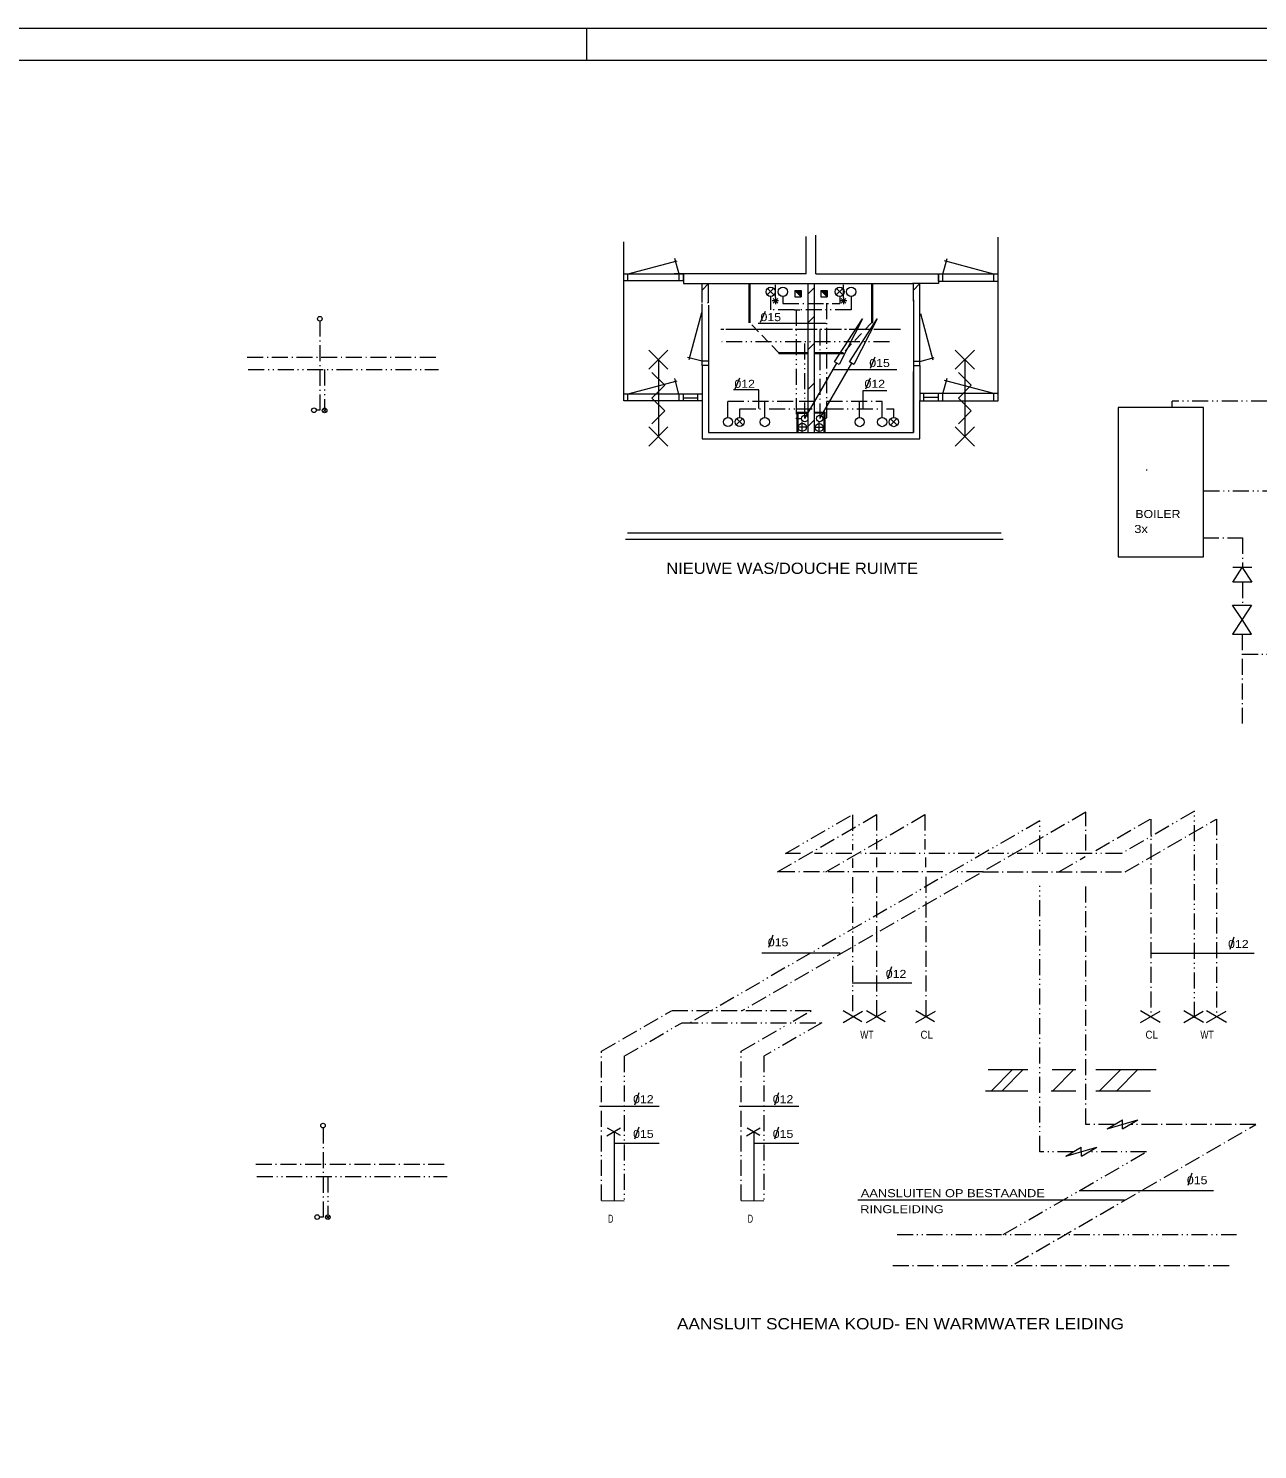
# Model space of a CAD drawing. Extents: x 295824 to 414724, y 24924 to 109024.
# Drawn here: x 355274 to 393674, y 64629 to 109024 of the extents above; entities that cross this region are included whole.
import ezdxf

# ---------------------------------------------------------------- set-up
doc = ezdxf.new("R2010")
doc.units = 0
doc.header["$LTSCALE"] = 100
for name, pattern in [('DASH_DOUBLE_DOT', [9.2, 5, -1.2, 0.3, -1.2, 0.3, -1.2]), ('DOT_DASHED', [7.7, 5, -1.2, 0.3, -1.2]), ('MEDIUM_DASHED', [4.5, 3, -1.5])]:
    doc.linetypes.add(name, pattern=pattern)
for name, color, linetype, lineweight in [('1', 7, 'Continuous', 13), ('16', 7, 'Continuous', 13), ('30', 7, 'Continuous', 13), ('61', 7, 'Continuous', 13)]:
    doc.layers.add(name, color=color, linetype=linetype, lineweight=lineweight)

msp = doc.modelspace()

# ---------------------------------------------------------------- hatches: boundary and pattern name
at = {"layer": '1'}
for points in [[(379418.1, 100633.9), (379218.1, 100833.9), (379418.1, 100833.9)], [(380224.2, 100633.9), (380024.2, 100833.9), (380224.2, 100833.9)]]:
    msp.add_hatch(color=256, dxfattribs=at).paths.add_polyline_path(points)

# ---------------------------------------------------------------- linework, layer by layer
for p, q in [((372723.6, 108023.8), (372723.6, 109023.8)), ((379870, 101352.7), (379870, 102562.3)), ((373870.5, 97608.1), (373873.8, 102362.2)), ((379570, 101352.7), (379570, 102529)), ((385568.8, 97615.9), (385568.8, 102497.8)), ((374009.9, 101355.3), (375544.5, 101766.5)), ((375599.1, 101351), (375469, 101836.4)), ((383842.7, 101347), (383972.8, 101832.4)), ((385431.8, 101351.3), (383897.2, 101762.5)), ((374004.8, 101134.9), (374004.8, 101354.9)), ((379570, 101352.7), (375450, 101352.7)), ((375604.8, 101134.9), (375604.8, 101354.9)), ((375738.8, 101134.9), (375738.8, 101355)), ((379870, 101352.7), (385568.7, 101352.7)), ((379870, 101352.7), (383754.9, 101352.7)), ((383703, 101131), (383703, 101351)), ((383837, 101131), (383837, 101351)), ((385437, 101131), (385437, 101351)), ((385568.8, 101131.7), (385568.8, 101352.4)), ((375734.5, 101135.7), (373873, 101135.7)), ((375740.5, 101052.7), (382920.9, 101052.7)), ((376320.1, 100458.9), (376320.1, 101052.7)), ((376320.2, 100851.2), (376521, 101052)), ((376517.6, 100464.5), (376517.6, 101052.7)), ((377785.5, 99826), (377785.5, 101042.9)), ((377821.5, 99826), (377821.5, 101042.9)), ((378611.3, 100615.1), (378611.3, 101015.1)), ((379620, 101052.7), (379620, 99815.2)), ((379620.9, 100722.9), (379817.9, 100919.8)), ((379820, 101052.7), (379820, 100575.7)), ((380740.2, 100615.1), (380740.2, 101015.1)), ((381621.1, 99838.3), (381621.1, 101047.9)), ((381657.1, 99838.3), (381657.1, 101047.9)), ((382920.9, 100504.8), (382920.9, 101053.4)), ((382921.2, 100851.2), (383122, 101052)), ((383120.4, 100521.4), (383120.4, 101052.7)), ((383707.2, 101131.7), (385568.8, 101131.7)), ((376319.7, 98492.6), (376319.7, 100418)), ((376489, 100447.3), (376518.2, 100476.6)), ((376519.7, 100374.5), (376519.7, 98492.6)), ((378711.3, 100515.1), (378511.3, 100515.1)), ((378682, 100585.9), (378540.5, 100444.4)), ((378682, 100444.4), (378540.5, 100585.9)), ((378611.3, 100615.1), (378611.3, 100415.1)), ((379820, 100629.6), (379820, 96402.7)), ((380840.2, 100515.1), (380640.2, 100515.1)), ((380810.9, 100585.9), (380669.5, 100444.4)), ((380810.9, 100444.4), (380669.5, 100585.9)), ((380740.2, 100615.1), (380740.2, 100415.1)), ((382920, 100548.5), (382920, 98491.9)), ((383120.2, 99693.6), (383120.2, 100570.2)), ((376300, 100144.2), (375906.4, 98675)), ((379620, 99979.6), (379620, 96402.7)), ((379620.9, 99827.7), (379817.9, 100024.7)), ((383147.1, 100115.4), (383533.2, 98674.3)), ((381621.1, 99838.3), (381657.1, 99838.3)), ((383120, 98490.3), (383120, 99786.1)), ((379620.9, 98982.6), (379817.9, 99179.6)), ((374653.8, 98376.3), (375253.8, 98976.3)), ((375253.8, 98376.3), (374653.8, 98976.3)), ((374953.8, 98676.3), (374953.8, 96276.3)), ((376320.2, 98624.6), (375865.6, 98746.4)), ((376519.5, 98626.6), (376320.8, 98626.6)), ((379619.3, 98854.3), (378718.6, 98854.3)), ((380722, 98890.3), (379821.9, 98890.3)), ((380722, 98854.3), (379821.9, 98854.3)), ((380722, 98890.3), (380722, 98854.3)), ((382920.2, 98625.9), (383118.9, 98625.9)), ((383119.4, 98623.9), (383574.1, 98745.7)), ((384229.2, 98376.3), (384829.2, 98976.3)), ((384829.2, 98376.3), (384229.2, 98976.3)), ((384529.2, 98676.3), (384529.2, 96276.3)), ((376519.7, 98492.6), (376319.7, 98492.6)), ((376320, 98487.5), (376320, 96913.2)), ((382920, 98491.9), (383120, 98491.9)), ((383120, 98491.9), (383120, 97602.7)), ((374007.5, 97607), (375542.1, 98018.2)), ((375596.6, 97602.7), (375466.5, 98088.1)), ((379620.9, 97742.7), (379817.9, 97939.7)), ((383842.7, 97610.4), (383972.8, 98095.9)), ((385431.8, 97614.8), (383897.2, 98025.9)), ((374002.3, 97386.7), (374002.3, 97606.7)), ((375602.3, 97386.7), (375602.3, 97606.7)), ((375736.3, 97386.7), (375736.3, 97606.7)), ((375737.9, 97488.2), (376187.3, 97488.2)), ((376187.3, 97386.7), (376187.3, 97606.7)), ((376320, 97402.7), (376320, 96202.7)), ((383120, 96202.7), (383120, 97402.7)), ((383252, 97394.4), (383252, 97614.4)), ((383701.4, 97495.9), (383252, 97495.9)), ((383703, 97394.4), (383703, 97614.4)), ((383837, 97394.4), (383837, 97614.4)), ((385437, 97394.4), (385437, 97614.4)), ((379283.4, 97034.7), (379619, 97034.7)), ((379283.4, 97034.7), (379283.4, 96407.2)), ((379313.4, 97004.7), (379621.3, 97004.7)), ((379313.4, 97004.7), (379313.4, 96406.6)), ((379623.7, 96586.7), (379818.3, 96781.2)), ((379821.3, 97037.4), (380159.6, 97037.4)), ((380129.8, 97007.1), (379823.1, 97007.1)), ((380129.8, 96403.9), (380129.8, 97007.1)), ((380159.6, 96402.7), (380159.6, 97037.4)), ((374653.8, 95976.3), (375253.8, 96576.3)), ((375253.8, 95976.3), (374653.8, 96576.3)), ((379869.6, 96402.7), (380247.8, 96402.7)), ((379896.8, 96402.7), (382920, 96402.7)), ((384229.2, 95976.3), (384829.2, 96576.3)), ((384829.2, 95976.3), (384229.2, 96576.3)), ((376320, 96202.7), (380270, 96202.7)), ((379788.1, 96202.7), (383120, 96202.7)), ((385660.9, 93254.8), (373993.5, 93254.8)), ((379569.2, 93054.8), (373926.9, 93054.8)), ((385720.9, 93054.8), (379158.9, 93054.8)), ((388974, 74651.8), (389937.5, 74926.6)), ((389455.4, 74648.3), (389450, 74926.6)), ((373572.9, 74556.8), (373572.9, 72400.9)), ((377936.9, 74556.8), (377936.9, 72400.9)), ((387687.3, 73797.5), (388650.8, 74072.3)), ((388168.7, 73794), (388163.3, 74072.3)), ((373177.8, 72405.6), (373885.8, 72397.2)), ((377541.8, 72405.6), (378249.8, 72397.2))]:
    msp.add_line(p, q, dxfattribs=at)
at = {"layer": '1', "linetype": 'MEDIUM_DASHED'}
for p, q in [((378703.9, 98896.4), (377820.1, 99826.4)), ((381612.4, 99823), (380724.4, 98888.4))]:
    msp.add_line(p, q, dxfattribs=at)
at = {"layer": '1', "linetype": 'DOT_DASHED'}
for p, q in [((379629.6, 96568.9), (379301.5, 96568.9)), ((379451.2, 96406.5), (379451.2, 96734.6)), ((380149.1, 96554), (379821, 96554)), ((380149.4, 96554), (379821.3, 96554)), ((379978.9, 96405.5), (379978.9, 96724.2))]:
    msp.add_line(p, q, dxfattribs=at)
at = {"layer": '1'}
for points in [[(414723.6, 109023.8), (304995.6, 109023.8), (295823.6, 109023.8)], [(304995.6, 25923.8), (413723.6, 25923.8), (413723.6, 108023.8), (304995.6, 108023.8)], [(373873, 101135.7), (373873, 101356.4), (375739.7, 101356.4)], [(379570, 101352.7), (375740.5, 101352.7), (375740.5, 101052.7)], [(383702.1, 101352.4), (383702.1, 101052.7), (382891.3, 101052.7)], [(379218.1, 100833.9), (379418.1, 100833.9), (379418.1, 100633.9)], [(380024.2, 100833.9), (380224.2, 100833.9), (380224.2, 100633.9)], [(376520, 98854.3), (376520, 96402.7), (380280, 96402.7)], [(379619.3, 98890.3), (378718.6, 98890.3), (378718.6, 98854.3)], [(374753.8, 98276.3), (375153.8, 97876.3), (374753.8, 97476.3), (375153.8, 97076.3), (374753.8, 96676.3)], [(382920, 98491.9), (382920, 96402.7), (382920, 98302.7)], [(384329.2, 98276.3), (384729.2, 97876.3), (384329.2, 97476.3), (384729.2, 97076.3), (384329.2, 96676.3)]]:
    msp.add_lwpolyline(points, dxfattribs=at)
for points in [[(379218.1, 100833.9), (379218.1, 100633.9), (379418.1, 100633.9)], [(379418.1, 100633.9), (379218.1, 100833.9), (379418.1, 100833.9)], [(380024.2, 100833.9), (380024.2, 100633.9), (380224.2, 100633.9)], [(380224.2, 100633.9), (380024.2, 100833.9), (380224.2, 100833.9)], [(373870.5, 97387.4), (373870.5, 97608.1), (376319.1, 97608.1), (376319.1, 97387.4)], [(385568.8, 97395.1), (385568.8, 97615.9), (383120.2, 97615.9), (383120.2, 97395.1)]]:
    msp.add_lwpolyline(points, close=True, dxfattribs=at)
for centre in [(379451.3, 96567.2), (379980.2, 96555.4)]:
    msp.add_circle(centre, 125, dxfattribs=at)
at = {"layer": '30'}
for p, q in [((378555.7, 100904.3), (378353.4, 100702)), ((378361.4, 100900.2), (378564.1, 100697.5)), ((380712.7, 100904.3), (380510.4, 100702)), ((380518.4, 100900.2), (380721.1, 100697.5)), ((378288.7, 100185.9), (378138.8, 99835.8)), ((380187.6, 99802.5), (378072.1, 99802.5)), ((379526.8, 96838.7), (380526.8, 98570.7)), ((379993.2, 96838.7), (380993.2, 98570.7)), ((381720.1, 98752.5), (381570.2, 98402.4)), ((380387.5, 98369.1), (382403, 98369.1)), ((377489.1, 98102.4), (377339.2, 97752.4)), ((381570.2, 98102.4), (381420.2, 97752.4)), ((364578.2, 97041.5), (364476.9, 97142.9)), ((364580.3, 97138.7), (364479.1, 97037.5)), ((377589.6, 96837.7), (377387.3, 96635.4)), ((377395.3, 96833.6), (377598, 96630.9)), ((382405.3, 96833.8), (382203, 96631.5)), ((382211, 96829.6), (382413.7, 96626.9)), ((393497.3, 92179.7), (392897.3, 92179.7)), ((378531.1, 80698.9), (378397.8, 80315.5)), ((392935.1, 80637.9), (392801.9, 80254.6)), ((380630.3, 80141.2), (378181.8, 80141.2)), ((390335.3, 80138.8), (393565.3, 80138.8)), ((382241.7, 79704.6), (382108.4, 79321.3)), ((381006.3, 79205.5), (382871.9, 79205.5)), ((380723.2, 78341.7), (381308.4, 78003.8)), ((380723.2, 77975), (381335.6, 78328.6)), ((381456.1, 78341.7), (382041.3, 78003.8)), ((381456.1, 77975), (382068.5, 78328.6)), ((382997, 78341.7), (383582.2, 78003.8)), ((382997, 77975), (383609.4, 78328.6)), ((390014.4, 78341.7), (390632, 77985.1)), ((390014.4, 77975), (390626.8, 78328.6)), ((391366.7, 78341.7), (391984.3, 77985.1)), ((391366.7, 77975), (391979, 78328.6)), ((392082.9, 78341.7), (392700.5, 77985.1)), ((392082.9, 77975), (392695.2, 78328.6)), ((385260.8, 76499.5), (386493.4, 76499.5)), ((386010.4, 76491.2), (385368.9, 75849.7)), ((386343.5, 76491.2), (385702, 75849.7)), ((387259.6, 76499.5), (387992.5, 76499.5)), ((387925.9, 76491.2), (387284.4, 75849.7)), ((388625.4, 76499.5), (390507.6, 76499.5)), ((389391.6, 76491.2), (388750.2, 75849.7)), ((389924.6, 76491.2), (389283.2, 75849.7)), ((374346.5, 75774.6), (374213.3, 75391.3)), ((378710.5, 75774.6), (378577.3, 75391.3)), ((385177.5, 75832.9), (386493.4, 75832.9)), ((387226.3, 75832.9), (387992.5, 75832.9)), ((388625.4, 75832.9), (390324.4, 75832.9)), ((373111.2, 75354.2), (374976.7, 75354.2)), ((377475.2, 75354.2), (379340.7, 75354.2)), ((373341.3, 74433.6), (373774, 74683.4)), ((373358.9, 74682.4), (373764.3, 74448.3)), ((374346.5, 74704.7), (374213.3, 74321.3)), ((377705.3, 74433.6), (378138, 74683.4)), ((377722.8, 74682.4), (378128.2, 74448.3)), ((378710.5, 74704.7), (378577.3, 74321.3)), ((388974, 74651.8), (389450, 74926.6)), ((389455.4, 74648.3), (389937.5, 74926.6)), ((373572.9, 74205.5), (374976.7, 74205.5)), ((377936.9, 74205.5), (379340.7, 74205.5)), ((387687.3, 73797.5), (388163.3, 74072.3)), ((388168.7, 73794), (388650.8, 74072.3)), ((391623.1, 73265.6), (391489.8, 72882.3)), ((389520, 72417.2), (381189, 72417.2)), ((392298.9, 72707.9), (388101.5, 72707.9)), ((364678.7, 71838.9), (364577.3, 71940.2)), ((364680.8, 71936), (364579.6, 71834.9))]:
    msp.add_line(p, q, dxfattribs=at)
at = {"layer": '30', "linetype": 'DASH_DOUBLE_DOT'}
for p, q in [((378460.8, 100653.6), (378460.8, 100234.8)), ((380975.9, 100653.6), (380975.9, 100234.8)), ((379193.7, 100234.8), (378460.8, 100234.8)), ((379193.7, 100234.8), (379368.5, 100234.8)), ((379260.3, 100234.8), (379260.3, 96829.5)), ((380975.9, 100234.8), (379368.5, 100234.8)), ((382519.7, 99617.9), (376906.2, 99617.9)), ((382169.9, 99234.5), (376939.6, 99234.5)), ((379526.8, 96838.7), (379526.8, 99217.9)), ((362143, 98367.3), (368089.4, 98367.3)), ((364526.5, 98367.3), (364526.5, 97167.3)), ((405933, 97381.8), (391003.1, 97381.8)), ((391003.1, 97184.3), (391003.1, 97381.8)), ((377494.7, 96873.6), (377494.7, 97141.2)), ((379426.8, 96829.5), (379260.3, 96829.5)), ((380236.3, 97141.2), (382310.4, 97141.2)), ((382310.4, 96869.7), (382310.4, 97141.2)), ((391984.8, 94576.2), (395663, 94576.2)), ((378930.1, 83253.8), (381023, 84462.1)), ((381023, 84462.1), (381023, 83358.4)), ((386875.2, 84273.1), (375947.2, 77963.8)), ((386875.2, 83315), (386875.2, 84273.1)), ((379396.5, 83253.8), (378930.1, 83253.8)), ((381002.3, 83253.8), (379829.6, 83253.8)), ((381023, 83088.8), (381023, 82805.4)), ((389422.7, 83253.8), (381278.2, 83253.8)), ((381023, 82505.4), (381023, 78236.7)), ((386875.2, 73930.7), (386875.2, 82238.8)), ((373885.8, 76920.5), (375692.9, 77963.8)), ((373885.8, 76920.5), (373885.8, 72397.2)), ((385729.1, 71345.1), (390207.4, 73930.7)), ((387918.1, 73930.7), (386875.2, 73930.7)), ((390207.4, 73930.7), (388405.5, 73930.7)), ((362410, 73164.6), (368356.4, 73164.6)), ((364627, 73164.6), (364627, 71948)), ((382411.3, 71345.1), (393015.6, 71345.1))]:
    msp.add_line(p, q, dxfattribs=at)
at = {"layer": '30', "linetype": 'DOT_DASHED'}
for p, q in [((380209.7, 100437.8), (380209.7, 96846.2)), ((380617.8, 100653.6), (380617.8, 100430.7)), ((364376.7, 99895.6), (364376.7, 97095.3)), ((382186.6, 99617.9), (377011.4, 99617.9)), ((379993.2, 99617.9), (379993.2, 96888.7)), ((362109.7, 98750.6), (368056, 98750.6)), ((377128.3, 96873.7), (377128.3, 97382.8)), ((377128.3, 97382.8), (379193.7, 97382.8)), ((378279.6, 96869.8), (378279.6, 97382.8)), ((379351.9, 97382.8), (379859.9, 97382.8)), ((380209.7, 97382.8), (381944, 97382.8)), ((381236.1, 96869.8), (381236.1, 97382.8)), ((381944, 96869.8), (381944, 97382.8)), ((364376.7, 97095.3), (364270.4, 97095.3)), ((380084.8, 96846.2), (380209.7, 96846.2)), ((390219.1, 95209.2), (390219.1, 95242.5)), ((391968.1, 93109.1), (393200.8, 93109.1)), ((393200.8, 93109.1), (393200.8, 92205.8)), ((393200.8, 91729.7), (393200.8, 91009)), ((393187.2, 90105), (393187.2, 87310.6)), ((393187.2, 89477.3), (409364.8, 89477.3)), ((388309.5, 84538.8), (377563.3, 78334.5)), ((378680.3, 82678.3), (381771.6, 84463.1)), ((380189.8, 82678.3), (383281.1, 84463.1)), ((381771.6, 84463.1), (381771.6, 83372)), ((383281.1, 84463.1), (383281.1, 83372)), ((388309.5, 83338.5), (388309.5, 84538.8)), ((388616.5, 83343.3), (390319.6, 84326.5)), ((390335.3, 84326.5), (390335.3, 78145)), ((381771.6, 83122.1), (381771.6, 82822.1)), ((383296.8, 83122.1), (383296.8, 82822.1)), ((387464.8, 82678.3), (388292.1, 83156)), ((383838, 82678.3), (378680.3, 82678.3)), ((385076.4, 82678.3), (384287.7, 82678.3)), ((381771.6, 82522.1), (381771.6, 78150.8)), ((383312.5, 82522.1), (383312.5, 78150.8)), ((388309.5, 74786.5), (388309.5, 82272.1)), ((379728.2, 78334.5), (375364.2, 78334.5)), ((379162.1, 78007.6), (379728.2, 78334.5)), ((377541.8, 77072.2), (378898.2, 77855.2)), ((377541.8, 72405.6), (377541.8, 77072.2)), ((364477.1, 74692.9), (364477.1, 71892.7)), ((386087.7, 70435.5), (393623.9, 74786.5)), ((389207.4, 74786.5), (388309.5, 74786.5)), ((393623.9, 74786.5), (389694.9, 74786.5)), ((362376.7, 73548), (368323.1, 73548)), ((364477.1, 71892.7), (364370.8, 71892.7)), ((382278.1, 70378.8), (392882.4, 70378.8))]:
    msp.add_line(p, q, dxfattribs=at)
for points in [[(378843.9, 100653.6), (378843.9, 100430.7), (380617.8, 100430.7)], [(385076.4, 82678.3), (389540.3, 82678.3), (392395.1, 84326.5), (392395.1, 78145)], [(373177.8, 72405.6), (373177.8, 77072.2), (375364.2, 78334.5)]]:
    msp.add_lwpolyline(points, dxfattribs=at)
at = {"layer": '30'}
for points in [[(381326.8, 99956.7), (380598.8, 98528.7), (380454.8, 98612.7)], [(381793.2, 99956.7), (381065.2, 98528.7), (380921.2, 98612.7)], [(389319.6, 92517.4), (391984.8, 92517.4), (391984.8, 97184.3), (389319.6, 97184.3)], [(393497.3, 91729.7), (392897.3, 91729.7), (393197.3, 92179.7)], [(392887.2, 91005), (393487.2, 91005), (393187.2, 90555)], [(392887.2, 90105), (393487.2, 90105), (393187.2, 90555)]]:
    msp.add_lwpolyline(points, close=True, dxfattribs=at)
for points in [[(378088.8, 97148.2), (378088.8, 97731.6), (377305.9, 97731.6)], [(381353.6, 97148.2), (381353.6, 97714.9), (382086.5, 97714.9)]]:
    msp.add_lwpolyline(points, dxfattribs=at)
at = {"layer": '30', "linetype": 'DASH_DOUBLE_DOT'}
for points in [[(377494.7, 97141.2), (379260.3, 97141.2), (379886.5, 97141.2)], [(391699, 78114.3), (391699, 84568), (389422.7, 83253.8)], [(375692.9, 77963.8), (380056.9, 77963.8), (378249.8, 76920.5), (378249.8, 72397.2)]]:
    msp.add_lwpolyline(points, dxfattribs=at)
at = {"layer": '30'}
for centre, radius in [((378460.8, 100796.9), 143.3), ((378843.9, 100796.9), 143.3), ((380617.8, 100796.9), 143.3), ((380975.9, 100796.9), 143.3), ((364376.7, 99953.6), 71.7), ((364193.4, 97095.3), 71.7), ((364526.6, 97091.2), 71.7), ((377128.3, 96730.3), 143.3), ((377494.7, 96730.3), 143.3), ((378279.6, 96726.4), 143.3), ((379526.8, 96838.1), 100), ((379993.2, 96838.1), 100), ((381244.4, 96726.4), 143.3), ((381944, 96726.4), 143.3), ((382310.4, 96726.4), 143.3), ((364477.1, 74751), 71.7), ((364293.9, 71892.7), 71.7), ((364627, 71888.6), 71.7)]:
    msp.add_circle(centre, radius, dxfattribs=at)

# ---------------------------------------------------------------- texts
at = {"layer": '16'}
for s, width, p in [('015', 1.15, (378145.2, 99879.8)), ('015', 1.15, (381543.3, 98446.4)), ('012', 1.15, (377329, 97796.4)), ('012', 1.15, (381393.4, 97796.4)), ('015', 1.15, (378374.2, 80351.5)), ('012', 1.15, (392753.2, 80297.2)), ('012', 1.15, (382059.8, 79363.9)), ('WT', 0.8, (381260.3, 77463.9)), ('CL', 0.9, (383144.8, 77463.9)), ('CL', 0.9, (390173.2, 77463.9)), ('WT', 0.8, (391887.1, 77463.9)), ('012', 1.15, (374164.7, 75449.6)), ('012', 1.15, (378528.6, 75449.6)), ('015', 1.15, (374164.7, 74364)), ('015', 1.15, (378528.6, 74364)), ('015', 1.15, (391466.2, 72918.2)), ('AANSLUITEN OP BESTAANDE ', 1.2, (381277, 72514)), ('D', 0.65, (373377.8, 71716.1)), ('D', 0.65, (377741.8, 71716.1)), ('RINGLEIDING', 1.2, (381260.3, 72014))]:
    msp.add_text(s, height=250, dxfattribs=dict(at, width=width)).set_placement(p)
at = {"layer": '30'}
for s, width, p in [('BOILER', 1.15, (389855.3, 93729.6)), ('3x', 1.2, (389822, 93262.9))]:
    msp.add_text(s, height=250, dxfattribs=dict(at, width=width)).set_placement(p)
at = {"layer": '61'}
for s, width, p in [('NIEUWE WAS/DOUCHE RUIMTE', 1.1, (375202.2, 91984.4)), ('AANSLUIT SCHEMA KOUD- EN WARMWATER LEIDING', 1.15, (375535.4, 68384.6))]:
    msp.add_text(s, height=350, dxfattribs=dict(at, width=width)).set_placement(p)

doc.saveas('drawing.dxf')
